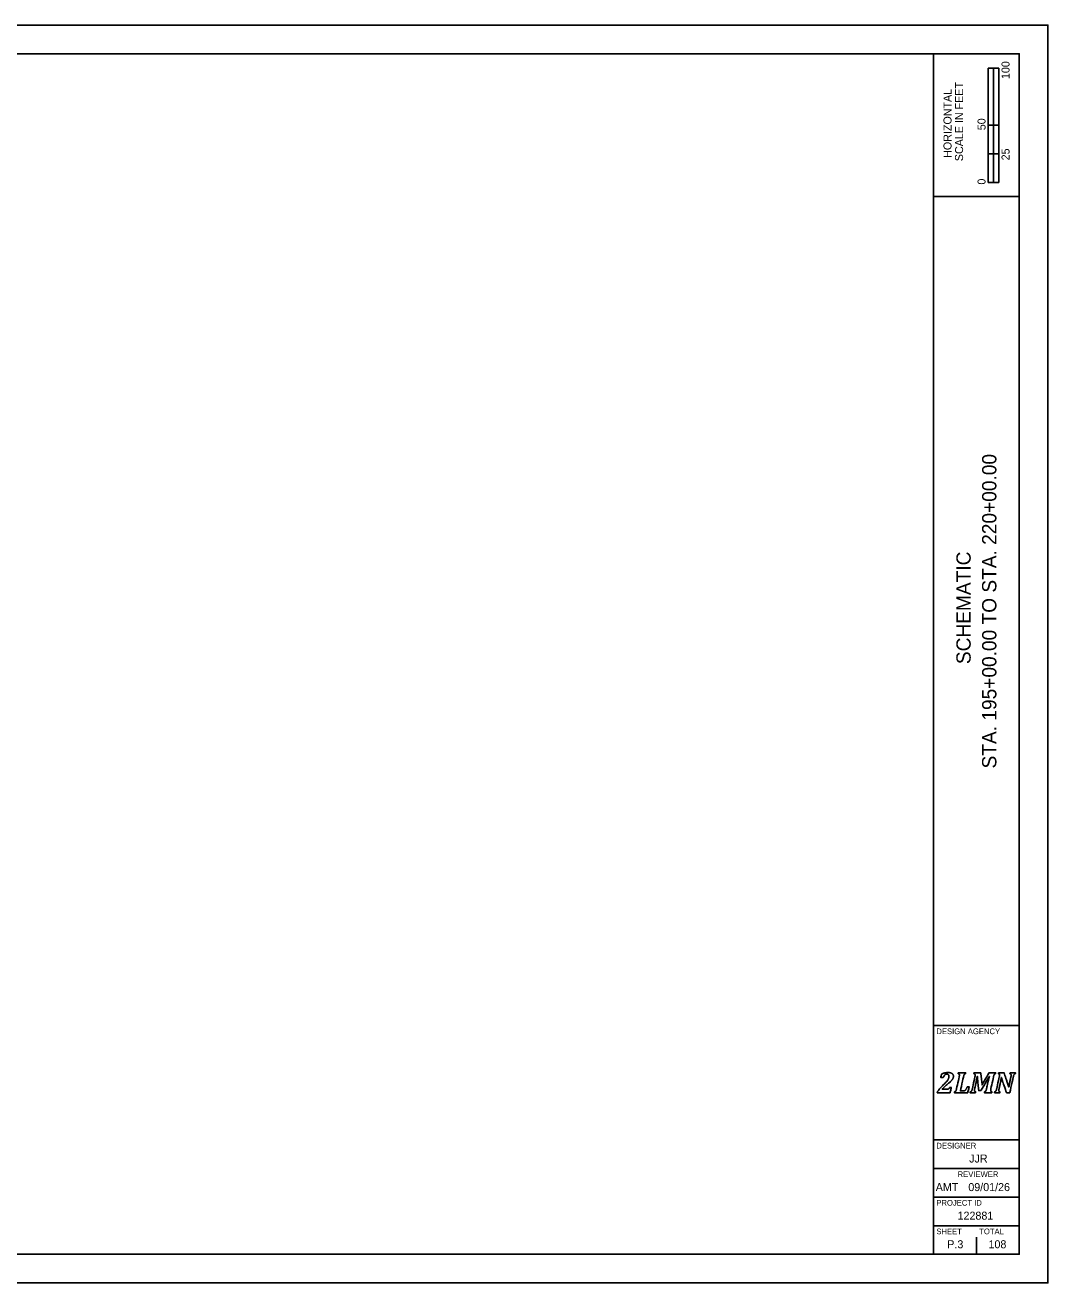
# Model space of a CAD drawing. Extents: x -1.8 to 34, y 0 to 22.
# Drawn here: x 16.11 to 34, y 0 to 22 of the extents above; entities that cross this region are included whole.
import ezdxf

# ---------------------------------------------------------------- set-up
doc = ezdxf.new("R2010")
doc.units = 0
for name, color, linetype in [('SH_Border', 7, 'Continuous'), ('SH_Cut_Line', 7, 'Continuous'), ('SH_Data', 7, 'Continuous')]:
    doc.layers.add(name, color=color, linetype=linetype)

msp = doc.modelspace()

# ---------------------------------------------------------------- linework, layer by layer
at = {"layer": 'SH_Border'}
for p, q in [((32, 0.5), (32, 21.5)), ((32, 19), (33.5, 19)), ((32, 4.5), (33.5, 4.5)), ((32, 2.5), (33.5, 2.5)), ((32, 2), (33.5, 2)), ((32, 1.5), (33.5, 1.5)), ((32, 1), (33.5, 1))]:
    msp.add_line(p, q, dxfattribs=at)
msp.add_lwpolyline([(1.5, 21.5), (33.5, 21.5), (33.5, 0.5), (1.5, 0.5)], close=True, dxfattribs=at)
at = {"layer": 'SH_Cut_Line'}
msp.add_lwpolyline([(0, 0), (34, 0), (34, 22), (0, 22)], close=True, dxfattribs=at)
at = {"layer": 'SH_Data'}
for p, q in [((32.957, 19.25), (32.957, 21.25)), ((33.144, 21.25), (32.957, 21.25)), ((32.957, 20.25), (32.957, 21.25)), ((32.957, 21.25), (33.05, 21.25)), ((33.05, 21.25), (33.051, 21.25)), ((33.051, 21.25), (33.051, 20.25)), ((33.144, 21.25), (33.144, 19.25)), ((33.051, 20.25), (32.957, 20.25)), ((33.143, 20.25), (33.05, 20.25)), ((33.05, 20.25), (33.05, 19.75)), ((33.143, 19.75), (33.143, 20.25)), ((33.05, 19.75), (32.957, 19.75)), ((32.957, 19.75), (32.957, 19.25)), ((33.05, 19.25), (33.05, 19.75)), ((33.05, 19.75), (33.143, 19.75)), ((33.144, 19.25), (32.957, 19.25)), ((32.957, 19.25), (33.05, 19.25)), ((32.75, 3.5), (32.75, 3.5)), ((32.375, 0.675), (32.375, 0.675)), ((32.75, 0.5), (32.75, 0.8))]:
    msp.add_line(p, q, dxfattribs=at)
for points in [[(32.237, 3.388), (32.246, 3.388), (32.253, 3.389), (32.258, 3.39), (32.263, 3.392), (32.267, 3.394), (32.27, 3.397), (32.273, 3.401), (32.277, 3.408), (32.281, 3.417), (32.281, 3.417), (32.312, 3.417), (32.312, 3.417), (32.312, 3.417), (32.29, 3.326), (32.29, 3.326), (32.29, 3.326), (32.066, 3.326), (32.066, 3.326), (32.066, 3.326), (32.069, 3.343), (32.069, 3.343), (32.078, 3.358), (32.091, 3.375), (32.106, 3.394), (32.122, 3.412), (32.144, 3.435), (32.172, 3.462), (32.197, 3.486), (32.217, 3.506), (32.23, 3.521), (32.243, 3.537), (32.253, 3.551), (32.259, 3.566), (32.266, 3.58), (32.269, 3.595), (32.269, 3.61), (32.269, 3.622), (32.266, 3.632), (32.26, 3.64), (32.253, 3.647), (32.245, 3.65), (32.234, 3.65), (32.22, 3.65), (32.208, 3.646), (32.198, 3.636), (32.188, 3.627), (32.18, 3.613), (32.172, 3.593), (32.172, 3.593), (32.126, 3.593), (32.126, 3.593), (32.126, 3.593), (32.14, 3.654), (32.14, 3.654), (32.166, 3.663), (32.188, 3.669), (32.205, 3.673), (32.223, 3.676), (32.24, 3.678), (32.258, 3.678), (32.278, 3.678), (32.295, 3.675), (32.309, 3.669), (32.322, 3.664), (32.332, 3.656), (32.339, 3.646), (32.345, 3.637), (32.348, 3.626), (32.348, 3.613), (32.348, 3.602), (32.346, 3.591), (32.342, 3.581), (32.339, 3.571), (32.333, 3.56), (32.324, 3.549), (32.315, 3.539), (32.304, 3.526), (32.289, 3.513), (32.275, 3.499), (32.254, 3.482), (32.228, 3.46), (32.216, 3.45), (32.202, 3.438), (32.188, 3.425), (32.174, 3.412), (32.162, 3.4), (32.154, 3.391), (32.154, 3.391), (32.153, 3.388), (32.153, 3.388), (32.153, 3.388), (32.237, 3.388), (32.237, 3.388)], [(32.237, 3.388), (32.237, 3.388), (32.153, 3.388), (32.153, 3.388), (32.153, 3.388), (32.154, 3.391), (32.154, 3.391), (32.162, 3.4), (32.174, 3.412), (32.188, 3.425), (32.202, 3.438), (32.216, 3.45), (32.228, 3.46), (32.254, 3.482), (32.275, 3.499), (32.289, 3.513), (32.304, 3.526), (32.315, 3.539), (32.324, 3.549), (32.333, 3.56), (32.339, 3.571), (32.342, 3.581), (32.346, 3.591), (32.348, 3.602), (32.348, 3.613), (32.348, 3.626), (32.345, 3.637), (32.339, 3.646), (32.332, 3.656), (32.322, 3.664), (32.309, 3.669), (32.295, 3.675), (32.278, 3.678), (32.258, 3.678), (32.24, 3.678), (32.223, 3.676), (32.205, 3.673), (32.188, 3.669), (32.166, 3.663), (32.14, 3.654), (32.14, 3.654), (32.126, 3.593), (32.126, 3.593), (32.126, 3.593), (32.172, 3.593), (32.172, 3.593), (32.18, 3.613), (32.188, 3.627), (32.198, 3.636), (32.208, 3.646), (32.22, 3.65), (32.234, 3.65), (32.245, 3.65), (32.253, 3.647), (32.26, 3.64), (32.266, 3.632), (32.269, 3.622), (32.269, 3.61), (32.269, 3.595), (32.266, 3.58), (32.259, 3.566), (32.253, 3.551), (32.243, 3.537), (32.23, 3.521), (32.217, 3.506), (32.197, 3.486), (32.172, 3.462), (32.144, 3.435), (32.122, 3.412), (32.106, 3.394), (32.091, 3.375), (32.078, 3.358), (32.069, 3.343), (32.069, 3.343), (32.066, 3.326), (32.066, 3.326), (32.066, 3.326), (32.29, 3.326), (32.29, 3.326), (32.29, 3.326), (32.312, 3.417), (32.312, 3.417), (32.312, 3.417), (32.281, 3.417), (32.281, 3.417), (32.277, 3.408), (32.273, 3.401), (32.27, 3.397), (32.267, 3.394), (32.263, 3.392), (32.258, 3.39), (32.253, 3.389), (32.246, 3.388), (32.237, 3.388)], [(32.518, 3.356), (32.527, 3.356), (32.533, 3.357), (32.538, 3.358), (32.542, 3.36), (32.546, 3.362), (32.55, 3.365), (32.554, 3.368), (32.558, 3.372), (32.562, 3.377), (32.567, 3.382), (32.571, 3.388), (32.576, 3.397), (32.58, 3.405), (32.585, 3.415), (32.589, 3.427), (32.589, 3.427), (32.624, 3.427), (32.624, 3.427), (32.624, 3.427), (32.598, 3.326), (32.598, 3.326), (32.598, 3.326), (32.365, 3.326), (32.365, 3.326), (32.365, 3.326), (32.369, 3.343), (32.369, 3.343), (32.376, 3.345), (32.381, 3.348), (32.385, 3.351), (32.389, 3.355), (32.392, 3.36), (32.395, 3.366), (32.398, 3.373), (32.4, 3.382), (32.403, 3.395), (32.403, 3.395), (32.449, 3.605), (32.449, 3.605), (32.452, 3.615), (32.453, 3.625), (32.453, 3.635), (32.453, 3.642), (32.451, 3.647), (32.448, 3.651), (32.444, 3.654), (32.439, 3.656), (32.432, 3.657), (32.432, 3.657), (32.435, 3.674), (32.435, 3.674), (32.435, 3.674), (32.563, 3.674), (32.563, 3.674), (32.563, 3.674), (32.559, 3.657), (32.559, 3.657), (32.552, 3.655), (32.547, 3.652), (32.543, 3.649), (32.539, 3.645), (32.536, 3.64), (32.533, 3.634), (32.531, 3.627), (32.528, 3.618), (32.525, 3.605), (32.525, 3.605), (32.47, 3.356), (32.47, 3.356), (32.47, 3.356), (32.518, 3.356), (32.518, 3.356)], [(32.518, 3.356), (32.518, 3.356), (32.47, 3.356), (32.47, 3.356), (32.47, 3.356), (32.525, 3.605), (32.525, 3.605), (32.528, 3.618), (32.531, 3.627), (32.533, 3.634), (32.536, 3.64), (32.539, 3.645), (32.543, 3.649), (32.547, 3.652), (32.552, 3.655), (32.559, 3.657), (32.559, 3.657), (32.563, 3.674), (32.563, 3.674), (32.563, 3.674), (32.435, 3.674), (32.435, 3.674), (32.435, 3.674), (32.432, 3.657), (32.432, 3.657), (32.439, 3.656), (32.444, 3.654), (32.448, 3.651), (32.451, 3.647), (32.453, 3.642), (32.453, 3.635), (32.453, 3.625), (32.452, 3.615), (32.449, 3.605), (32.449, 3.605), (32.403, 3.395), (32.403, 3.395), (32.4, 3.382), (32.398, 3.373), (32.395, 3.366), (32.392, 3.36), (32.389, 3.355), (32.385, 3.351), (32.381, 3.348), (32.376, 3.345), (32.369, 3.343), (32.369, 3.343), (32.365, 3.326), (32.365, 3.326), (32.365, 3.326), (32.598, 3.326), (32.598, 3.326), (32.598, 3.326), (32.624, 3.427), (32.624, 3.427), (32.624, 3.427), (32.589, 3.427), (32.589, 3.427), (32.585, 3.415), (32.58, 3.405), (32.576, 3.397), (32.571, 3.388), (32.567, 3.382), (32.562, 3.377), (32.558, 3.372), (32.554, 3.368), (32.55, 3.365), (32.546, 3.362), (32.542, 3.36), (32.538, 3.358), (32.533, 3.357), (32.527, 3.356), (32.518, 3.356)], [(32.829, 3.674), (32.829, 3.674), (32.849, 3.461), (32.849, 3.461), (32.849, 3.461), (32.969, 3.674), (32.969, 3.674), (32.969, 3.674), (33.087, 3.674), (33.087, 3.674), (33.087, 3.674), (33.084, 3.657), (33.084, 3.657), (33.077, 3.655), (33.071, 3.652), (33.067, 3.649), (33.064, 3.645), (33.06, 3.64), (33.058, 3.634), (33.055, 3.627), (33.052, 3.618), (33.05, 3.605), (33.05, 3.605), (33.003, 3.395), (33.003, 3.395), (33.002, 3.39), (33.002, 3.387), (33.001, 3.384), (33.001, 3.382), (33.001, 3.379), (33, 3.376), (33, 3.373), (33, 3.369), (33, 3.365), (33, 3.358), (33.002, 3.353), (33.005, 3.349), (33.008, 3.346), (33.014, 3.344), (33.021, 3.343), (33.021, 3.343), (33.018, 3.326), (33.018, 3.326), (33.018, 3.326), (32.89, 3.326), (32.89, 3.326), (32.89, 3.326), (32.893, 3.343), (32.893, 3.343), (32.9, 3.345), (32.906, 3.348), (32.91, 3.351), (32.914, 3.355), (32.917, 3.36), (32.919, 3.366), (32.922, 3.373), (32.925, 3.382), (32.928, 3.395), (32.928, 3.395), (32.951, 3.502), (32.951, 3.502), (32.954, 3.513), (32.957, 3.529), (32.962, 3.548), (32.967, 3.568), (32.972, 3.588), (32.978, 3.609), (32.978, 3.609), (32.973, 3.609), (32.973, 3.609), (32.965, 3.594), (32.957, 3.579), (32.948, 3.563), (32.948, 3.563), (32.833, 3.364), (32.833, 3.364), (32.833, 3.364), (32.792, 3.364), (32.792, 3.364), (32.792, 3.364), (32.775, 3.518), (32.775, 3.518), (32.773, 3.537), (32.772, 3.554), (32.77, 3.569), (32.769, 3.583), (32.768, 3.597), (32.768, 3.611), (32.768, 3.611), (32.764, 3.611), (32.764, 3.611), (32.761, 3.596), (32.758, 3.578), (32.755, 3.558), (32.751, 3.538), (32.747, 3.521), (32.744, 3.507), (32.744, 3.507), (32.72, 3.395), (32.72, 3.395), (32.719, 3.39), (32.718, 3.387), (32.718, 3.384), (32.717, 3.382), (32.717, 3.379), (32.717, 3.376), (32.717, 3.373), (32.716, 3.369), (32.716, 3.365), (32.716, 3.358), (32.718, 3.353), (32.721, 3.349), (32.725, 3.346), (32.73, 3.344), (32.738, 3.343), (32.738, 3.343), (32.734, 3.326), (32.734, 3.326), (32.734, 3.326), (32.641, 3.326), (32.641, 3.326), (32.641, 3.326), (32.644, 3.343), (32.644, 3.343), (32.651, 3.345), (32.657, 3.348), (32.661, 3.351), (32.665, 3.355), (32.668, 3.36), (32.67, 3.366), (32.673, 3.373), (32.676, 3.382), (32.679, 3.395), (32.679, 3.395), (32.725, 3.605), (32.725, 3.605), (32.727, 3.615), (32.728, 3.625), (32.728, 3.635), (32.728, 3.642), (32.727, 3.647), (32.723, 3.651), (32.72, 3.654), (32.715, 3.656), (32.707, 3.657), (32.707, 3.657), (32.711, 3.674), (32.711, 3.674), (32.711, 3.674), (32.829, 3.674), (32.829, 3.674)], [(32.829, 3.674), (32.829, 3.674), (32.711, 3.674), (32.711, 3.674), (32.711, 3.674), (32.707, 3.657), (32.707, 3.657), (32.715, 3.656), (32.72, 3.654), (32.723, 3.651), (32.727, 3.647), (32.728, 3.642), (32.728, 3.635), (32.728, 3.625), (32.727, 3.615), (32.725, 3.605), (32.725, 3.605), (32.679, 3.395), (32.679, 3.395), (32.676, 3.382), (32.673, 3.373), (32.67, 3.366), (32.668, 3.36), (32.665, 3.355), (32.661, 3.351), (32.657, 3.348), (32.651, 3.345), (32.644, 3.343), (32.644, 3.343), (32.641, 3.326), (32.641, 3.326), (32.641, 3.326), (32.734, 3.326), (32.734, 3.326), (32.734, 3.326), (32.738, 3.343), (32.738, 3.343), (32.73, 3.344), (32.725, 3.346), (32.721, 3.349), (32.718, 3.353), (32.716, 3.358), (32.716, 3.365), (32.716, 3.369), (32.717, 3.373), (32.717, 3.376), (32.717, 3.379), (32.717, 3.382), (32.718, 3.384), (32.718, 3.387), (32.719, 3.39), (32.72, 3.395), (32.72, 3.395), (32.744, 3.507), (32.744, 3.507), (32.747, 3.521), (32.751, 3.538), (32.755, 3.558), (32.758, 3.578), (32.761, 3.596), (32.764, 3.611), (32.764, 3.611), (32.768, 3.611), (32.768, 3.611), (32.768, 3.597), (32.769, 3.583), (32.77, 3.569), (32.772, 3.554), (32.773, 3.537), (32.775, 3.518), (32.775, 3.518), (32.792, 3.364), (32.792, 3.364), (32.792, 3.364), (32.833, 3.364), (32.833, 3.364), (32.833, 3.364), (32.948, 3.563), (32.948, 3.563), (32.957, 3.579), (32.965, 3.594), (32.973, 3.609), (32.973, 3.609), (32.978, 3.609), (32.978, 3.609), (32.972, 3.588), (32.967, 3.568), (32.962, 3.548), (32.957, 3.529), (32.954, 3.513), (32.951, 3.502), (32.951, 3.502), (32.928, 3.395), (32.928, 3.395), (32.925, 3.382), (32.922, 3.373), (32.919, 3.366), (32.917, 3.36), (32.914, 3.355), (32.91, 3.351), (32.906, 3.348), (32.9, 3.345), (32.893, 3.343), (32.893, 3.343), (32.89, 3.326), (32.89, 3.326), (32.89, 3.326), (33.018, 3.326), (33.018, 3.326), (33.018, 3.326), (33.021, 3.343), (33.021, 3.343), (33.014, 3.344), (33.008, 3.346), (33.005, 3.349), (33.002, 3.353), (33, 3.358), (33, 3.365), (33, 3.369), (33, 3.373), (33, 3.376), (33.001, 3.379), (33.001, 3.382), (33.001, 3.384), (33.002, 3.387), (33.002, 3.39), (33.003, 3.395), (33.003, 3.395), (33.05, 3.605), (33.05, 3.605), (33.052, 3.618), (33.055, 3.627), (33.058, 3.634), (33.06, 3.64), (33.064, 3.645), (33.067, 3.649), (33.071, 3.652), (33.077, 3.655), (33.084, 3.657), (33.084, 3.657), (33.087, 3.674), (33.087, 3.674), (33.087, 3.674), (32.969, 3.674), (32.969, 3.674), (32.969, 3.674), (32.849, 3.461), (32.849, 3.461), (32.849, 3.461), (32.829, 3.674), (32.829, 3.674)], [(33.137, 3.674), (33.137, 3.674), (33.234, 3.674), (33.234, 3.674), (33.234, 3.674), (33.283, 3.53), (33.283, 3.53), (33.296, 3.49), (33.307, 3.456), (33.315, 3.426), (33.315, 3.426), (33.318, 3.426), (33.318, 3.426), (33.323, 3.455), (33.329, 3.488), (33.337, 3.523), (33.337, 3.523), (33.355, 3.605), (33.355, 3.605), (33.357, 3.615), (33.358, 3.625), (33.358, 3.635), (33.358, 3.642), (33.357, 3.647), (33.353, 3.651), (33.35, 3.654), (33.345, 3.656), (33.337, 3.657), (33.337, 3.657), (33.341, 3.674), (33.341, 3.674), (33.341, 3.674), (33.434, 3.674), (33.434, 3.674), (33.434, 3.674), (33.431, 3.657), (33.431, 3.657), (33.424, 3.655), (33.418, 3.652), (33.414, 3.649), (33.41, 3.645), (33.407, 3.64), (33.405, 3.634), (33.402, 3.627), (33.399, 3.618), (33.396, 3.605), (33.396, 3.605), (33.335, 3.326), (33.335, 3.326), (33.335, 3.326), (33.277, 3.326), (33.277, 3.326), (33.277, 3.326), (33.216, 3.504), (33.216, 3.504), (33.211, 3.518), (33.207, 3.531), (33.204, 3.543), (33.2, 3.556), (33.195, 3.571), (33.19, 3.59), (33.19, 3.59), (33.186, 3.59), (33.186, 3.59), (33.185, 3.579), (33.182, 3.563), (33.179, 3.543), (33.175, 3.523), (33.17, 3.501), (33.165, 3.478), (33.165, 3.478), (33.147, 3.395), (33.147, 3.395), (33.146, 3.39), (33.145, 3.387), (33.145, 3.384), (33.144, 3.382), (33.144, 3.379), (33.144, 3.376), (33.143, 3.373), (33.143, 3.369), (33.143, 3.365), (33.143, 3.358), (33.145, 3.353), (33.148, 3.349), (33.152, 3.346), (33.157, 3.344), (33.164, 3.343), (33.164, 3.343), (33.161, 3.326), (33.161, 3.326), (33.161, 3.326), (33.067, 3.326), (33.067, 3.326), (33.067, 3.326), (33.071, 3.343), (33.071, 3.343), (33.078, 3.345), (33.083, 3.348), (33.087, 3.351), (33.091, 3.355), (33.094, 3.36), (33.097, 3.366), (33.1, 3.373), (33.102, 3.382), (33.105, 3.395), (33.105, 3.395), (33.151, 3.605), (33.151, 3.605), (33.154, 3.615), (33.155, 3.625), (33.155, 3.635), (33.155, 3.642), (33.153, 3.647), (33.15, 3.651), (33.146, 3.654), (33.141, 3.656), (33.134, 3.657), (33.134, 3.657), (33.137, 3.674), (33.137, 3.674)], [(33.137, 3.674), (33.137, 3.674), (33.134, 3.657), (33.134, 3.657), (33.141, 3.656), (33.146, 3.654), (33.15, 3.651), (33.153, 3.647), (33.155, 3.642), (33.155, 3.635), (33.155, 3.625), (33.154, 3.615), (33.151, 3.605), (33.151, 3.605), (33.105, 3.395), (33.105, 3.395), (33.102, 3.382), (33.1, 3.373), (33.097, 3.366), (33.094, 3.36), (33.091, 3.355), (33.087, 3.351), (33.083, 3.348), (33.078, 3.345), (33.071, 3.343), (33.071, 3.343), (33.067, 3.326), (33.067, 3.326), (33.067, 3.326), (33.161, 3.326), (33.161, 3.326), (33.161, 3.326), (33.164, 3.343), (33.164, 3.343), (33.157, 3.344), (33.152, 3.346), (33.148, 3.349), (33.145, 3.353), (33.143, 3.358), (33.143, 3.365), (33.143, 3.369), (33.143, 3.373), (33.144, 3.376), (33.144, 3.379), (33.144, 3.382), (33.145, 3.384), (33.145, 3.387), (33.146, 3.39), (33.147, 3.395), (33.147, 3.395), (33.165, 3.478), (33.165, 3.478), (33.17, 3.501), (33.175, 3.523), (33.179, 3.543), (33.182, 3.563), (33.185, 3.579), (33.186, 3.59), (33.186, 3.59), (33.19, 3.59), (33.19, 3.59), (33.195, 3.571), (33.2, 3.556), (33.204, 3.543), (33.207, 3.531), (33.211, 3.518), (33.216, 3.504), (33.216, 3.504), (33.277, 3.326), (33.277, 3.326), (33.277, 3.326), (33.335, 3.326), (33.335, 3.326), (33.335, 3.326), (33.396, 3.605), (33.396, 3.605), (33.399, 3.618), (33.402, 3.627), (33.405, 3.634), (33.407, 3.64), (33.41, 3.645), (33.414, 3.649), (33.418, 3.652), (33.424, 3.655), (33.431, 3.657), (33.431, 3.657), (33.434, 3.674), (33.434, 3.674), (33.434, 3.674), (33.341, 3.674), (33.341, 3.674), (33.341, 3.674), (33.337, 3.657), (33.337, 3.657), (33.345, 3.656), (33.35, 3.654), (33.353, 3.651), (33.357, 3.647), (33.358, 3.642), (33.358, 3.635), (33.358, 3.625), (33.357, 3.615), (33.355, 3.605), (33.355, 3.605), (33.337, 3.523), (33.337, 3.523), (33.329, 3.488), (33.323, 3.455), (33.318, 3.426), (33.318, 3.426), (33.315, 3.426), (33.315, 3.426), (33.307, 3.456), (33.296, 3.49), (33.283, 3.53), (33.283, 3.53), (33.234, 3.674), (33.234, 3.674), (33.234, 3.674), (33.137, 3.674), (33.137, 3.674)]]:
    msp.add_open_spline(points, degree=3, dxfattribs=at)

# ---------------------------------------------------------------- texts
for s, height, p in [('100', 0.14, (33.33, 21.057)), ('SCALE IN FEET', 0.14, (32.517, 19.621)), ('HORIZONTAL', 0.14, (32.315, 19.679)), ('50', 0.14, (32.91, 20.162)), ('25', 0.14, (33.33, 19.635)), ('0', 0.14, (32.91, 19.211)), ('STA. 195+00.00 TO STA. 220+00.00', 0.25, (33.1, 8.998)), ('SCHEMATIC', 0.25, (32.65, 10.823))]:
    msp.add_text(s, height=height, rotation=90, dxfattribs=at).set_placement(p)
for s, height, p in [('DESIGN AGENCY', 0.1, (32.05, 4.35)), ('DESIGNER', 0.1, (32.05, 2.35)), ('JJR', 0.14, (32.624, 2.105)), ('REVIEWER', 0.1, (32.422, 1.85)), ('AMT', 0.14, (32.039, 1.605)), ('09/01/26', 0.14, (32.609, 1.605)), ('PROJECT ID', 0.1, (32.05, 1.35)), ('122881', 0.14, (32.421, 1.105)), ('SHEET', 0.1, (32.05, 0.85)), ('TOTAL', 0.1, (32.8, 0.85)), ('P.3', 0.14, (32.241, 0.605)), ('108', 0.14, (32.962, 0.605))]:
    msp.add_text(s, height=height, dxfattribs=at).set_placement(p)

doc.saveas('drawing.dxf')
